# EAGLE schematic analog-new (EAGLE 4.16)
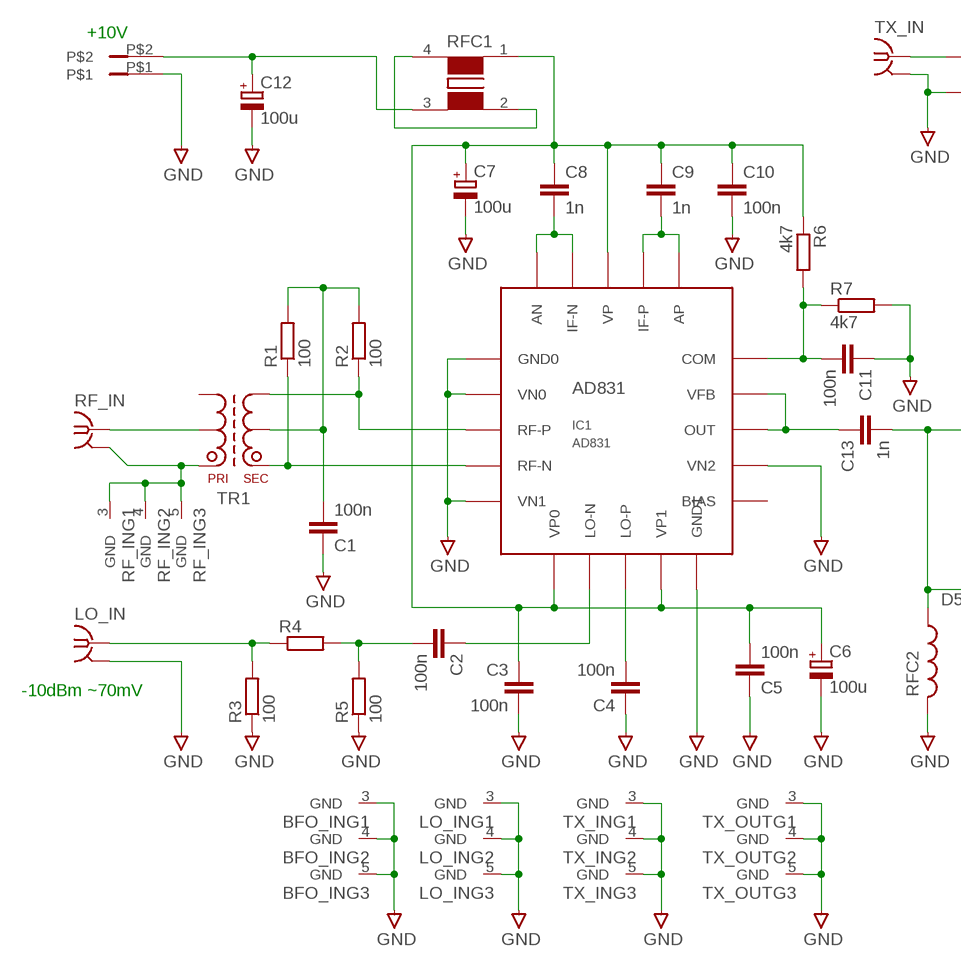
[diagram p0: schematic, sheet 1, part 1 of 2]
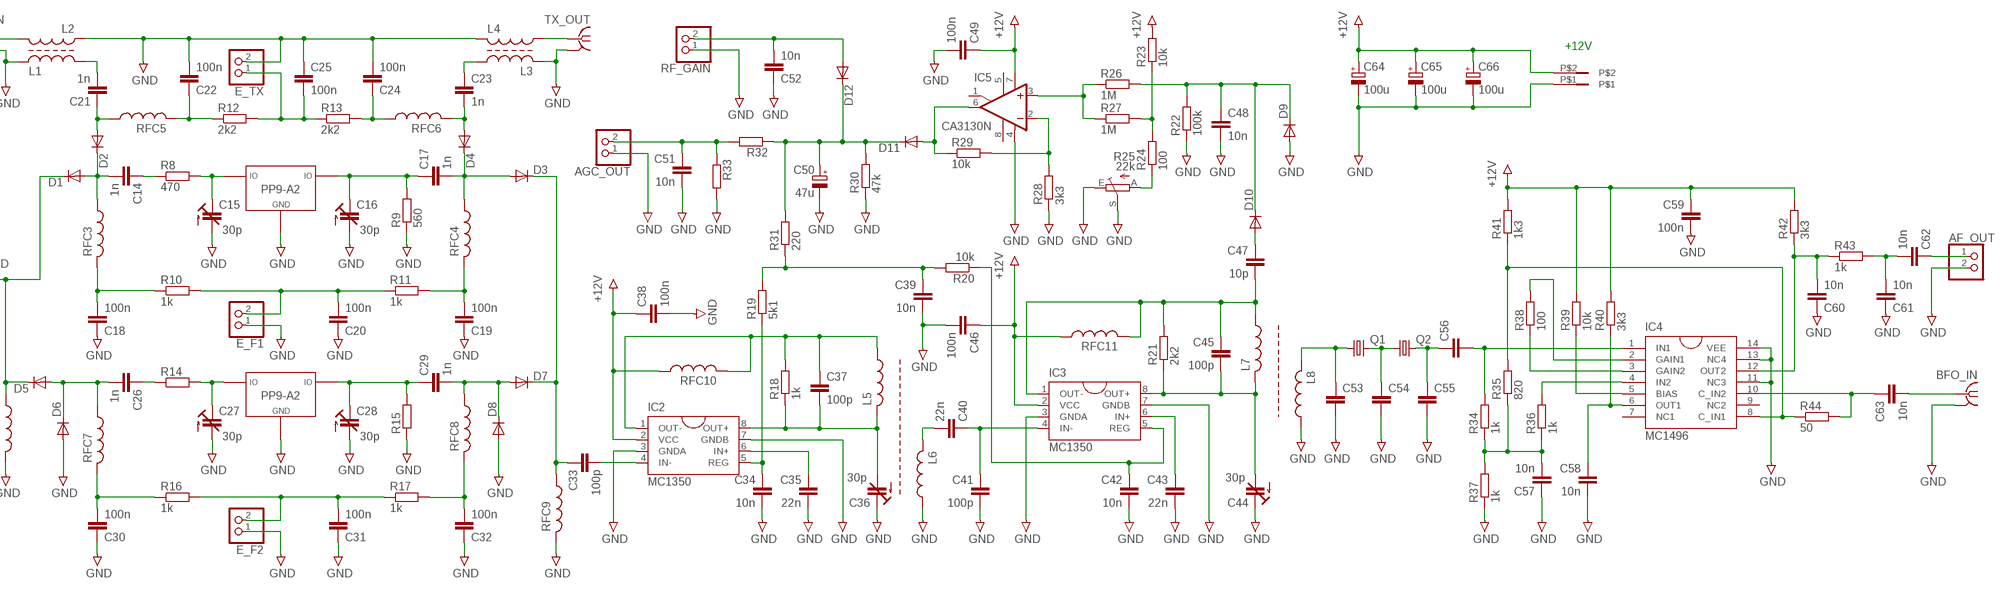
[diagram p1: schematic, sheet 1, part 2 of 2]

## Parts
+-5V  RIACON-2  [RIACON-2]
+-5V1  RIACON-2  [RIACON-2]
AF_OUT  PINHD-1X2  [1X02]
AGC_OUT  PINHD-1X2  [1X02]
BFO_IN  BU-SMA-V  [BU-SMA-V]
C1  100n  C-EUC1206K  [C1206K]
C2  100n  C-EUC1206K  [C1206K]
C3  100n  C-EUC1206K  [C1206K]
C4  100n  C-EUC1206K  [C1206K]
C5  100n  C-EUC1206K  [C1206K]
C6  100u  CPOL-EUE2.5-7  [E2,5-7]
C7  100u  CPOL-EUE2.5-7  [E2,5-7]
C8  1n  C-EUC0805  [C0805]
C9  1n  C-EUC0805  [C0805]
C10  100n  C-EUC1206K  [C1206K]
C11  100n  C-EUC1206K  [C1206K]
C12  100u  CPOL-EUE2.5-7  [E2,5-7]
C13  1n  C-EUC1206K  [C1206K]
C14  1n  C-EUC1206K  [C1206K]
C15  30p  C-TRIMMTZBX4  [CTRIMTZBX4]
C16  30p  C-TRIMMTZBX4  [CTRIMTZBX4]
C17  1n  C-EUC1206K  [C1206K]
C18  100n  C-EUC1206K  [C1206K]
C19  100n  C-EUC1206K  [C1206K]
C20  100n  C-EUC1206K  [C1206K]
C21  1n  C-EUC1206K  [C1206K]
C22  100n  C-EUC1206K  [C1206K]
C23  1n  C-EUC1206K  [C1206K]
C24  100n  C-EUC1206K  [C1206K]
C25  100n  C-EUC1206K  [C1206K]
C26  1n  C-EUC1206K  [C1206K]
C27  30p  C-TRIMMTZBX4  [CTRIMTZBX4]
C28  30p  C-TRIMMTZBX4  [CTRIMTZBX4]
C29  1n  C-EUC1206K  [C1206K]
C30  100n  C-EUC1206K  [C1206K]
C31  100n  C-EUC1206K  [C1206K]
C32  100n  C-EUC1206K  [C1206K]
C33  100p  C-EUC1206K  [C1206K]
C34  10n  C-EUC1206K  [C1206K]
C35  22n  C-EUC1206K  [C1206K]
C36  30p  C-TRIMM3040.428  [CTRIM3040.428]
C37  100p  C-EUC1206K  [C1206K]
C38  100n  C-EUC1206K  [C1206K]
C39  10n  C-EUC1206K  [C1206K]
C40  22n  C-EUC1206K  [C1206K]
C41  100p  C-EUC1206K  [C1206K]
C42  10n  C-EUC1206K  [C1206K]
C43  22n  C-EUC1206K  [C1206K]
C44  30p  C-TRIMM3040.428  [CTRIM3040.428]
C45  100p  C-EUC1206K  [C1206K]
C46  100n  C-EUC1206K  [C1206K]
C47  10p  C-EUC1206K  [C1206K]
C48  10n  C-EUC1206K  [C1206K]
C49  100n  C-EUC1206K  [C1206K]
C50  47u  CPOL-EUE2.5-7  [E2,5-7]
C51  10n  C-EUC1206K  [C1206K]
C52  10n  C-EUC1206K  [C1206K]
C53  C-EUC1206K  [C1206K]
C54  C-EUC1206K  [C1206K]
C55  C-EUC1206K  [C1206K]
C56  C-EUC1206K  [C1206K]
C57  10n  C-EUC0805  [C0805]
C58  10n  C-EUC1206K  [C1206K]
C59  100n  C-EUC1206K  [C1206K]
C60  10n  C-EUC1206K  [C1206K]
C61  10n  C-EUC1206K  [C1206K]
C62  10n  C-EUC1206K  [C1206K]
C63  10n  C-EUC1206K  [C1206K]
C64  100u  CPOL-EUE2.5-7  [E2,5-7]
C65  100u  CPOL-EUE2.5-7  [E2,5-7]
C66  100u  CPOL-EUE2.5-7  [E2,5-7]
D1  DIODE-SOD323-W  [SOD323-W]
D2  DIODE-SOD323-W  [SOD323-W]
D3  DIODE-SOD323-W  [SOD323-W]
D4  DIODE-SOD323-W  [SOD323-W]
D5  DIODE-SOD323-W  [SOD323-W]
D6  DIODE-SOD323-W  [SOD323-W]
D7  DIODE-SOD323-W  [SOD323-W]
D8  DIODE-SOD323-W  [SOD323-W]
D9  DIODE-C1702-05  [C1702-05]
D10  DIODE-C1702-05  [C1702-05]
D11  DIODE-SOD80C  [SOD80C]
D12  DIODE-SOD80C  [SOD80C]
E_F1  PINHD-1X2  [1X02]
E_F2  PINHD-1X2  [1X02]
E_TX  PINHD-1X2  [1X02]
F1  PP9  [PP9]
F2  PP9  [PP9]
IC1  AD831  [PLCC20S]
IC2  MC1350  [DIL08]
IC3  MC1350  [DIL08]
IC4  MC1496  [DIL14]
IC5  CA3130N  [DIL08]
L1  L-US0204/5  [0204/5]
L2  L-US0204/5  [0204/5]
L3  L-US0204/5  [0204/5]
L4  L-US0204/5  [0204/5]
L5  L-US0204/5  [0204/5]
L6  L-US0204/5  [0204/5]
L7  L-US0204/5  [0204/5]
L8  L-US0204/5  [0204/5]
LO_IN  BU-SMA-V  [BU-SMA-V]
Q1  CRYTALHC49U70  [HC49U70]
Q2  CRYTALHC49U70  [HC49U70]
R1  100  R-EU_R1206  [R1206]
R2  100  R-EU_R1206  [R1206]
R3  100  R-EU_R1206  [R1206]
R4  R-EU_R1206  [R1206]
R5  100  R-EU_R1206  [R1206]
R6  4k7  R-EU_R1206  [R1206]
R7  4k7  R-EU_R1206  [R1206]
R8  470  R-EU_R1206  [R1206]
R9  560  R-EU_R1206  [R1206]
R10  1k  R-EU_R1206  [R1206]
R11  1k  R-EU_R1206  [R1206]
R12  2k2  R-EU_R1206  [R1206]
R13  2k2  R-EU_R1206  [R1206]
R14  R-EU_R1206  [R1206]
R15  R-EU_R1206  [R1206]
R16  1k  R-EU_R1206  [R1206]
R17  1k  R-EU_R1206  [R1206]
R18  1k  R-EU_R1206  [R1206]
R19  5k1  R-EU_R1206  [R1206]
R20  10k  R-EU_R1206  [R1206]
R21  2k2  R-EU_R1206  [R1206]
R22  100k  R-EU_R1206  [R1206]
R23  10k  R-EU_R1206  [R1206]
R24  100  R-EU_R1206  [R1206]
R25  22k  TRIM_EU-CA6V  [CA6V]
R26  1M  R-EU_R1206  [R1206]
R27  1M  R-EU_R1206  [R1206]
R28  3k3  R-EU_R0805  [R0805]
R29  10k  R-EU_R0805  [R0805]
R30  47k  R-EU_R1206  [R1206]
R31  220  R-EU_R1206  [R1206]
R32  R-EU_R1206  [R1206]
R33  R-EU_R1206  [R1206]
R34  1k  R-EU_R0805  [R0805]
R35  820  R-EU_R1206  [R1206]
R36  1k  R-EU_R0805  [R0805]
R37  1k  R-EU_R0805  [R0805]
R38  100  R-EU_R1206  [R1206]
R39  10k  R-EU_R1206  [R1206]
R40  3k3  R-EU_R1206  [R1206]
R41  1k3  R-EU_R1206  [R1206]
R42  3k3  R-EU_R1206  [R1206]
R43  1k  R-EU_R1206  [R1206]
R44  50  R-EU_R1206  [R1206]
RF_GAIN  PINHD-1X2  [1X02]
RF_IN  BU-SMA-V  [BU-SMA-V]
RFC1  WE-CMS  [WE-CMS_7427521]
RFC2  L-US0207/7  [0207/7]
RFC3  L-US0207/7  [0207/7]
RFC4  L-US0207/7  [0207/7]
RFC5  L-US0207/7  [0207/7]
RFC6  L-US0207/7  [0207/7]
RFC7  L-US0207/7  [0207/7]
RFC8  L-US0207/7  [0207/7]
RFC9  L-US0207/7  [0207/7]
RFC10  L-US0207/7  [0207/7]
RFC11  L-US0207/7  [0207/7]
TR1  TT1-6  [MINICIRCUITS-W38]
TX_IN  BU-SMA-V  [BU-SMA-V]
TX_OUT  BU-SMA-V  [BU-SMA-V]

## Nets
C62: C61.2 C62.2 R43.2
N$1: C2.1 IC1.10(LO-N)
N$2: C14.1 R8.1
N$3: LO_IN.1 R3.2 R4.1
N$4: RF_IN.2(GND) RF_IN.3(GND) RF_IN.4(GND) RF_IN.5(GND) TR1.4(P1)
N$5: C9.2 IC1.19(AP) IC1.20(IF-P)
N$6: C8.2 IC1.2(IF-N) IC1.3(AN)
N$7: C2.2 R4.2 R5.2
N$8: C26.1 R14.1
N$9: C14.2 D1.A D2.C RFC3.1
N$11: IC1.6(RF-P) R2.1 TR1.1(S2)
N$12: +-5V.P$2 C12.+ RFC1.3
N$13: RF_IN.1 TR1.5(PT)
N$17: C13.1 IC1.16(OUT) IC1.17(VFB)
N$25: C15.1(E) F2.IO1 R8.2
N$26: C16.1(E) C17.1 F2.IO2 R9.2
N$27: C17.2 D3.A D4.C RFC4.1
N$28: C19.2 R11.2 RFC4.2
N$29: C18.2 R10.1 RFC3.2
N$31: C20.2 E_F1.2 R10.2 R11.1
N$32: C21.1 D2.A RFC5.1
N$34: C23.2 D4.A RFC6.2
N$35: C24.1 R13.2 RFC6.1
N$36: C25.2 E_TX.1 R12.2 R13.1
N$37: C22.1 R12.1 RFC5.2
N$38: IC1.7(RF-N) R1.1 TR1.3(S1)
N$39: C21.2 L1.1
N$40: L2.1 TX_IN.1
N$41: C23.1 L3.1
N$42: L4.1 TX_OUT.1
N$44: C13.2 D1.C D5.C RFC2.1
N$45: C26.2 D5.A D6.C RFC7.1
N$46: C27.1(E) F1.IO1 R14.2
N$47: C29.2 D7.A D8.C RFC8.1
N$49: C28.1(E) C29.1 F1.IO2 R15.2
N$51: C33.1 D3.C D7.C RFC9.1
N$53: C32.2 R17.2 RFC8.2
N$54: C31.2 E_F2.2 R16.2 R17.1
N$55: C1.2 R1.2 R2.2 TR1.2(ST)
N$61: C4.2 IC1.11(LO-P)
N$63: C11.2 IC1.18(COM) R6.2 R7.1
N$83: RFC1.2 RFC1.4
N$146: C30.2 R16.1 RFC7.2
N$178: C3.1 C5.2 C6.+ C7.+ C8.1 C9.1 C10.1 IC1.1(VP) IC1.9(VP0) IC1.12(VP1) R6.1 RFC1.1
N$309: C33.2 IC2.4(IN-)
N$310: C43.1 IC3.6(IN+)
N$311: C37.1 IC2.1(OUT-) L5.1 R18.2 RFC10.2
N$312: C35.1 IC2.6(IN+)
N$313: C52.2 D12.A RF_GAIN.2
N$314: C40.2 L6.2
N$315: C40.1 C41.1 IC3.4(IN-)
N$316: C34.1 IC2.5(REG) R19.1
N$317: C44.2(A) C45.2 IC3.8(OUT+) L7.2 R21.1
N$318: C45.1 C47.2 IC3.1(OUT-) L7.1 R21.2 RFC11.2
N$319: C39.1 R19.2 R20.2 R31.1
N$320: C47.1 D10.A
N$327: C48.1 D9.C D10.C R22.2 R26.2
N$328: C42.1 IC3.5(REG) R20.1
N$330: R23.1 R24.2 R27.2
N$331: R24.1 R25.A
N$332: IC5.3(+IN) R26.1 R27.1
N$333: IC5.2(-IN) R28.2 R29.2
N$334: D11.A IC5.6(OUT) R29.1
N$335: C50.+ D11.C D12.C R30.2 R31.2 R32.1
N$336: C36.2(A) C37.2 IC2.8(OUT+) L5.2 R18.1
N$337: AGC_OUT.2 C51.1 R32.2 R33.1
N$338: C53.1 L8.2 Q1.1
N$339: C54.1 Q1.2 Q2.1
N$340: C55.1 C56.1 Q2.2
N$341: C56.2 IC4.1(IN1) R34.2
N$342: IC4.4(IN2) R36.2
N$343: IC4.3(GAIN2) R38.1
N$344: IC4.2(GAIN1) R38.2
N$346: IC4.8(C_IN1) R35.2 R41.1 R44.1
N$347: C60.2 IC4.12(OUT2) R42.1 R43.1
N$348: C63.1 IC4.10(C_IN2) R44.2
N$349: C58.1 IC4.6(OUT1) R40.1
N$350: BFO_IN.1 C63.2
N$351: IC4.5(BIAS) R39.1
N$353: AF_OUT.1 C62.1
N$408: C57.2 R34.1 R35.1 R36.1 R37.2
N$459: +-5V1.P$2 C38.1 C46.1 C49.1 C59.1 C64.+ C65.+ C66.+ IC2.2(VCC) IC3.2(VCC) IC5.7(V+) R23.2 R39.2 R40.2 R41.2 R42.2 RFC10.1 RFC11.1 ; supply symbol labelled +12V
N$509: +-5V1.P$1 +-5V.P$1 AF_OUT.2 AGC_OUT.1 BFO_IN.2(GND) BFO_IN.3(GND) BFO_IN.4(GND) BFO_IN.5(GND) C1.1 C3.2 C4.1 C5.1 C6.- C7.- C10.2 C11.1 C12.- C15.2(A) C16.2(A) C18.1 C19.1 C20.1 C22.2 C24.2 C25.1 C27.2(A) C28.2(A) C30.1 C31.1 C32.1 C34.2 C35.2 C36.1A(E) C38.2 C39.2 C41.2 C42.2 C43.2 C44.1A(E) C46.2 C48.2 C49.2 C50.- C51.2 C52.1 C53.2 C54.2 C55.2 C57.1 C58.2 C59.2 C60.1 C61.1 C64.- C65.- C66.- D6.A D8.A D9.A E_F1.1 E_F2.1 E_TX.2 F1.GND F2.GND IC1.4(GND0) IC1.5(VN0) IC1.8(VN1) IC1.13(GND1) IC1.15(VN2) IC2.3(GNDA) IC2.7(GNDB) IC3.3(GNDA) IC3.7(GNDB) IC4.11(NC3) IC4.13(NC4) IC4.14(VEE) IC5.4(V-) L1.2 L2.2 L3.2 L4.2 L6.1 L8.1 LO_IN.2(GND) LO_IN.3(GND) LO_IN.4(GND) LO_IN.5(GND) R3.1 R5.1 R7.2 R9.1 R15.1 R22.1 R25.E R25.S R28.1 R30.1 R33.2 R37.1 RF_GAIN.1 RFC2.2 RFC9.2 TX_IN.2(GND) TX_IN.3(GND) TX_IN.4(GND) TX_IN.5(GND) TX_OUT.2(GND) TX_OUT.3(GND) TX_OUT.4(GND) TX_OUT.5(GND) ; supply symbol labelled GND
Unconnected: IC1.14(BIAS) IC4.7(NC1) IC4.9(NC2) IC5.1(ON/CMP) IC5.5(ON) IC5.8(CMP) TR1.6(P2)

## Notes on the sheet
- +10V
- +12V
- -10dBm ~70mV

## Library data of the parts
+-5V +-5V1 = con-riacon:RIACON-2
AF_OUT AGC_OUT E_F1 E_F2 E_TX RF_GAIN = pinhead:PINHD-1X2: PIN HEADER
BFO_IN LO_IN RF_IN TX_IN TX_OUT = con-coax:BU-SMA-V: FEMALE SMA CONNECTOR Radiall distributor RS 112-3794
C1-C5 C8-C11 C13 C14 C17-C26 C29-C35 C37-C43 C45-C49 C51-C63 = rcl:C-EU: CAPACITOR, European symbol
C6 C7 C12 C50 C64-C66 = rcl:CPOL-EU: POLARIZED CAPACITOR, European symbol
C15 C16 C27 C28 C36 C44 = rcl:C-TRIMM: Trimm capacitor
D1-D12 = diode:DIODE-: DIODE
F1 F2 = digirex:PP9: Crystal filter PP9-A2 (XF-9B) 9MHz 2.4kHz SSB filter
IC1 = digirex:AD831: High-Performance, Low Distortion 500-MHz Mixer
IC2 IC3 = receiver:MC1350
IC4 = receiver:MC1496
IC5 = linear:CA3130: OP AMP
L1-L8 RFC2-RFC11 = rcl:L-US: INDUCTOR, American symbol
Q1 Q2 = crystal:CRYTAL: CRYSTAL
R1-R24 R26-R44 = rcl:R-EU_: RESISTOR, European symbol
R25 = pot:TRIM_EU-: POTENTIOMETER
RFC1 = receiver:WE-CMS: Common Mode SMD Bead - rated current up to 5 A - impedances up to 200 ohms - RDC: 3 mohms
TR1 = receiver:TT1-6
